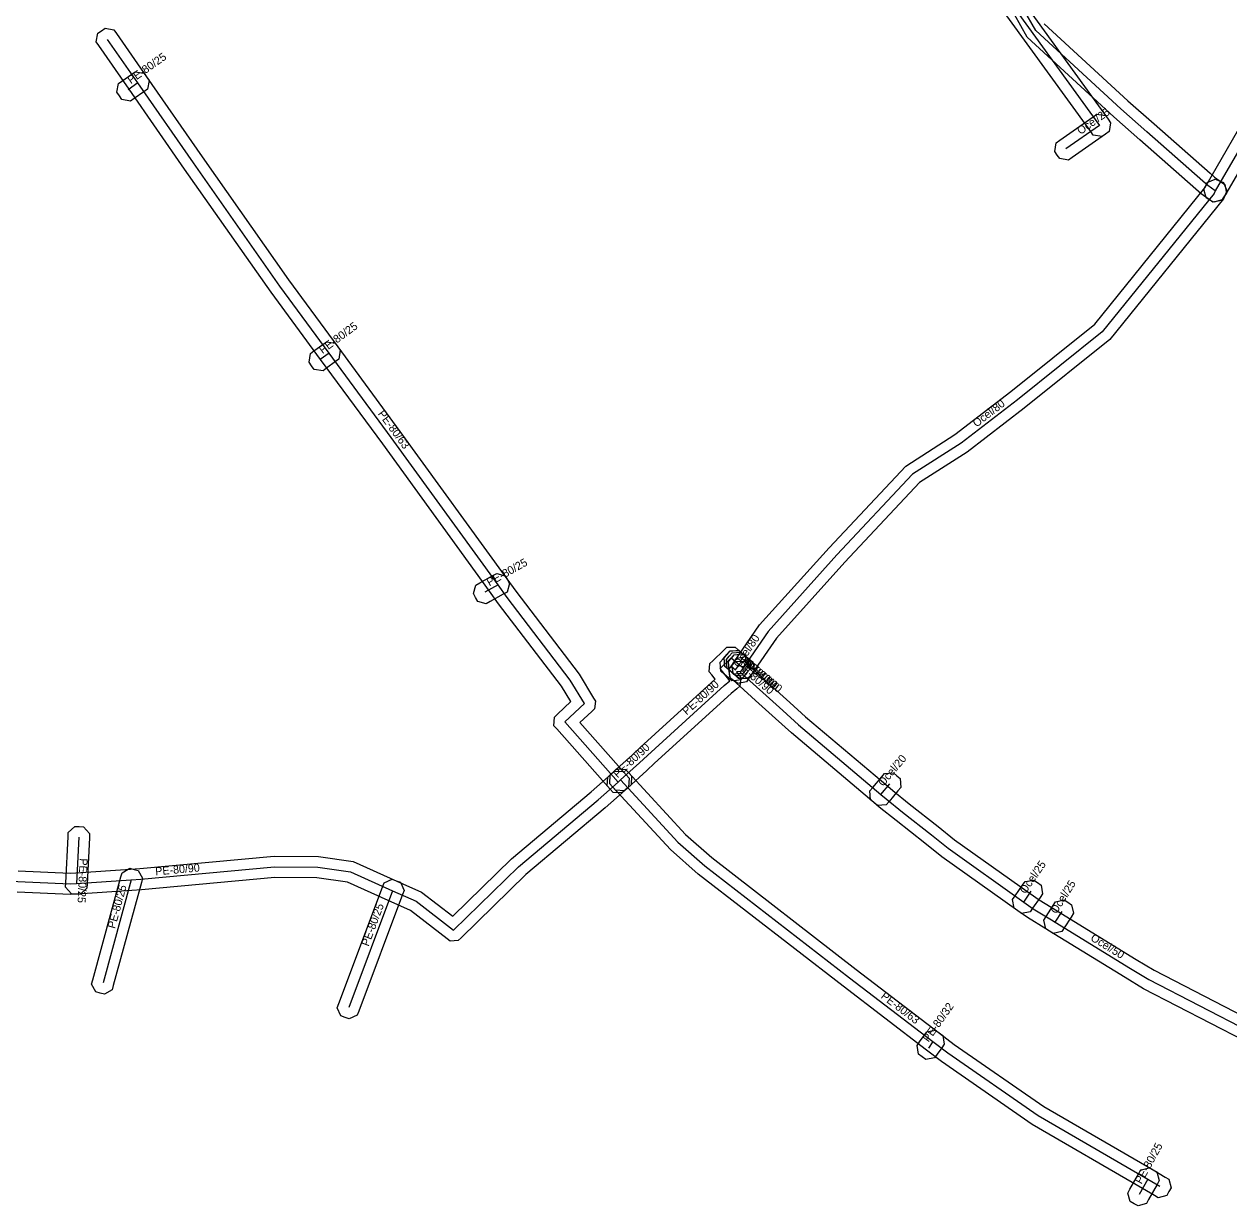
# Model space of a CAD drawing. Extents: x -569373 to -565022, y -1135090 to -1131496.
# Drawn here: x -565532.3 to -565419.4, y -1134096.5 to -1133985.7 of the extents above; entities that cross this region are included whole.
import ezdxf

# ---------------------------------------------------------------- set-up
doc = ezdxf.new("R2010")
doc.units = 0
for name, color, linetype in [('1', 7, 'Continuous'), ('24', 7, 'Continuous'), ('30', 7, 'Continuous')]:
    doc.layers.add(name, color=color, linetype=linetype)

msp = doc.modelspace()

# ---------------------------------------------------------------- linework, layer by layer
at = {"layer": '1'}
for points in [[(-565440.45, -1133981.063), (-565430.679, -1133994.584), (-565430.437, -1133994.92), (-565430.568, -1133995.738), (-565430.904, -1133995.981), (-565431.24, -1133996.223), (-565432.058, -1133996.092), (-565432.301, -1133995.756), (-565442.07, -1133982.237)], [(-565436.667, -1133985.641), (-565428.811, -1133992.877), (-565426.369, -1133995.03), (-565421.117, -1133999.661), (-565420.709, -1134000.024), (-565420.057, -1134000.481), (-565419.717, -1134000.718), (-565419.573, -1134001.534), (-565419.811, -1134001.873), (-565420.048, -1134002.213), (-565420.864, -1134002.357), (-565421.203, -1134002.119), (-565421.951, -1134001.596), (-565422.443, -1134001.159), (-565427.691, -1133996.53), (-565430.149, -1133994.363), (-565438.253, -1133986.899), (-565439.46, -1133984.762)], [(-565417.887, -1134080.99), (-565427.351, -1134076.122), (-565429.086, -1134075.056), (-565436.153, -1134070.713), (-565436.507, -1134070.496), (-565438.239, -1134069.436), (-565439.148, -1134068.796), (-565446.271, -1134063.729), (-565447.853, -1134062.473), (-565450.553, -1134060.323), (-565452.126, -1134059.072), (-565452.618, -1134058.652), (-565460.349, -1134052.113), (-565461.841, -1134050.762), (-565463.71, -1134049.073), (-565465.2, -1134047.733), (-565465.831, -1134047.162), (-565466.138, -1134046.884), (-565466.18, -1134046.056), (-565465.902, -1134045.749), (-565465.624, -1134045.442), (-565464.796, -1134045.4), (-565464.489, -1134045.678), (-565463.86, -1134046.247), (-565462.37, -1134047.587), (-565460.499, -1134049.278), (-565459.031, -1134050.607), (-565451.322, -1134057.128), (-565450.854, -1134057.528), (-565449.307, -1134058.757), (-565446.607, -1134060.907), (-565445.069, -1134062.131), (-565437.992, -1134067.164), (-565437.141, -1134067.764), (-565435.463, -1134068.79), (-565435.107, -1134069.007), (-565428.038, -1134073.352), (-565426.369, -1134074.378), (-565416.973, -1134079.21)], [(-565532.823, -1134065.052), (-565527.962, -1134065.268), (-565527.437, -1134065.232), (-565522.307, -1134064.892), (-565521.429, -1134064.833), (-565508.852, -1134063.69), (-565504.675, -1134063.721), (-565501.42, -1134064.19), (-565497.342, -1134066.007), (-565495.023, -1134067.046), (-565492.098, -1134069.298), (-565486.602, -1134063.929), (-565479.115, -1134057.634), (-565477.266, -1134055.984), (-565476.957, -1134055.708), (-565476.13, -1134055.755), (-565475.854, -1134056.064), (-565475.578, -1134056.373), (-565475.625, -1134057.2), (-565475.934, -1134057.476), (-565477.805, -1134059.146), (-565485.258, -1134065.411), (-565491.321, -1134071.335), (-565491.588, -1134071.596), (-565492.334, -1134071.64), (-565492.63, -1134071.412), (-565496.057, -1134068.774), (-565498.158, -1134067.833), (-565501.98, -1134066.13), (-565504.825, -1134065.719), (-565508.768, -1134065.69), (-565521.271, -1134066.827), (-565522.173, -1134066.888), (-565527.303, -1134067.228), (-565527.938, -1134067.272), (-565532.937, -1134067.048)]]:
    msp.add_lwpolyline(points, dxfattribs=at)
for points in [[(-565477.073, -1134057.703), (-565477.348, -1134057.393), (-565482.348, -1134051.753), (-565482.618, -1134051.449), (-565482.579, -1134050.635), (-565482.281, -1134050.358), (-565481.027, -1134049.191), (-565481.907, -1134047.734), (-565487.803, -1134040.026), (-565488.661, -1134038.836), (-565498.668, -1134025.03), (-565504.496, -1134017.102), (-565509.122, -1134010.814), (-565517.23, -1133999.263), (-565522.441, -1133991.76), (-565525.272, -1133987.68), (-565525.508, -1133987.34), (-565525.36, -1133986.524), (-565525.02, -1133986.288), (-565524.68, -1133986.052), (-565523.864, -1133986.2), (-565523.628, -1133986.54), (-565520.799, -1133990.62), (-565515.59, -1133998.117), (-565507.498, -1134009.646), (-565502.884, -1134015.918), (-565497.052, -1134023.85), (-565487.039, -1134037.664), (-565486.197, -1134038.834), (-565480.253, -1134046.606), (-565478.894, -1134048.853), (-565478.71, -1134049.157), (-565478.809, -1134049.86), (-565479.069, -1134050.102), (-565480.204, -1134051.157), (-565475.852, -1134056.067), (-565475.577, -1134056.377), (-565475.627, -1134057.203), (-565475.937, -1134057.478), (-565476.247, -1134057.753)], [(-565520.706, -1133991.77), (-565521.045, -1133992.008), (-565521.955, -1133992.648), (-565522.294, -1133992.886), (-565523.11, -1133992.744), (-565523.348, -1133992.405), (-565523.586, -1133992.066), (-565523.444, -1133991.25), (-565523.105, -1133991.012), (-565522.195, -1133990.372), (-565521.856, -1133990.134), (-565521.04, -1133990.276), (-565520.802, -1133990.615), (-565520.564, -1133990.954)], [(-565415.067, -1133993.714), (-565415.275, -1133994.072), (-565419.765, -1134001.802), (-565419.973, -1134002.16), (-565420.774, -1134002.373), (-565421.132, -1134002.165), (-565421.49, -1134001.957), (-565421.703, -1134001.156), (-565421.495, -1134000.798), (-565417.005, -1133993.068), (-565416.797, -1133992.71), (-565415.996, -1133992.497), (-565415.638, -1133992.705), (-565415.28, -1133992.913)], [(-565430.576, -1133995.75), (-565430.915, -1133995.988), (-565434.045, -1133998.188), (-565434.384, -1133998.426), (-565435.2, -1133998.284), (-565435.438, -1133997.945), (-565435.676, -1133997.606), (-565435.534, -1133996.79), (-565435.195, -1133996.552), (-565432.065, -1133994.352), (-565431.726, -1133994.114), (-565430.91, -1133994.256), (-565430.672, -1133994.595), (-565430.434, -1133994.934)], [(-565419.548, -1134001.303), (-565419.707, -1134001.685), (-565419.862, -1134002.057), (-565430.51, -1134015.232), (-565438.542, -1134021.676), (-565443.884, -1134025.789), (-565448.356, -1134028.655), (-565455.354, -1134036.117), (-565461.763, -1134043.24), (-565464.065, -1134046.596), (-565464.299, -1134046.937), (-565465.114, -1134047.089), (-565465.456, -1134046.855), (-565465.797, -1134046.621), (-565465.949, -1134045.806), (-565465.715, -1134045.464), (-565463.337, -1134042), (-565456.826, -1134034.763), (-565449.644, -1134027.105), (-565445.036, -1134024.151), (-565439.778, -1134020.104), (-565431.93, -1134013.808), (-565421.598, -1134001.023), (-565421.553, -1134000.915), (-565421.394, -1134000.533), (-565420.627, -1134000.218), (-565420.245, -1134000.377), (-565419.863, -1134000.536)], [(-565502.764, -1134017.071), (-565503.098, -1134017.316), (-565503.928, -1134017.926), (-565504.262, -1134018.171), (-565505.081, -1134018.046), (-565505.326, -1134017.712), (-565505.571, -1134017.378), (-565505.446, -1134016.559), (-565505.112, -1134016.314), (-565504.282, -1134015.704), (-565503.948, -1134015.459), (-565503.129, -1134015.584), (-565502.884, -1134015.918), (-565502.639, -1134016.252)], [(-565487.002, -1134038.923), (-565487.364, -1134039.124), (-565488.604, -1134039.814), (-565488.966, -1134040.015), (-565489.763, -1134039.788), (-565489.964, -1134039.426), (-565490.165, -1134039.064), (-565489.938, -1134038.267), (-565489.576, -1134038.066), (-565488.336, -1134037.376), (-565487.974, -1134037.175), (-565487.177, -1134037.402), (-565486.976, -1134037.764), (-565486.775, -1134038.126)], [(-565474.54, -1134053.497), (-565467.507, -1134047.098), (-565467.821, -1134046.692), (-565468.055, -1134046.39), (-565468.001, -1134045.629), (-565467.727, -1134045.363), (-565466.697, -1134044.363), (-565466.417, -1134044.092), (-565465.638, -1134044.07), (-565465.344, -1134044.325), (-565464.964, -1134044.655), (-565464.651, -1134044.927), (-565464.593, -1134045.753), (-565464.865, -1134046.066), (-565465.137, -1134046.379), (-565465.514, -1134046.405), (-565465.349, -1134046.618), (-565465.105, -1134046.933), (-565465.185, -1134047.726), (-565465.486, -1134047.986), (-565465.996, -1134048.428), (-565473.18, -1134054.963), (-565473.912, -1134055.655), (-565475.701, -1134057.264), (-565476.009, -1134057.541), (-565476.837, -1134057.497), (-565477.114, -1134057.189), (-565477.391, -1134056.881), (-565477.347, -1134056.053), (-565477.039, -1134055.776), (-565475.268, -1134054.185)], [(-565464.957, -1134044.662), (-565464.888, -1134044.724), (-565464.88, -1134044.723), (-565464.566, -1134044.993), (-565464.253, -1134045.264), (-565464.193, -1134046.09), (-565464.463, -1134046.404), (-565464.646, -1134046.615), (-565464.829, -1134046.837), (-565465.096, -1134047.16), (-565465.513, -1134047.196), (-565465.931, -1134047.233), (-565466.249, -1134046.961), (-565466.659, -1134046.611), (-565466.978, -1134046.338), (-565467.008, -1134045.919), (-565467.037, -1134045.501), (-565466.758, -1134045.187), (-565466.368, -1134044.747), (-565466.093, -1134044.437), (-565465.267, -1134044.387)], [(-565465.288, -1134044.38), (-565464.972, -1134044.648), (-565464.772, -1134044.818), (-565464.456, -1134045.086), (-565464.39, -1134045.912), (-565464.658, -1134046.228), (-565464.926, -1134046.544), (-565465.752, -1134046.61), (-565466.068, -1134046.342), (-565466.268, -1134046.172), (-565466.584, -1134045.904), (-565466.65, -1134045.078), (-565466.382, -1134044.762), (-565466.114, -1134044.446)], [(-565465.088, -1134044.55), (-565464.772, -1134044.818), (-565464.572, -1134044.988), (-565464.256, -1134045.256), (-565464.19, -1134046.082), (-565464.458, -1134046.398), (-565464.726, -1134046.714), (-565465.552, -1134046.78), (-565465.868, -1134046.512), (-565466.068, -1134046.342), (-565466.384, -1134046.074), (-565466.45, -1134045.248), (-565466.182, -1134044.932), (-565465.914, -1134044.616)], [(-565465.304, -1134047.03), (-565465.596, -1134046.738), (-565465.597, -1134046.737), (-565465.86, -1134046.518), (-565466.178, -1134046.253), (-565466.253, -1134045.428), (-565465.988, -1134045.11), (-565465.723, -1134044.792), (-565464.898, -1134044.717), (-565464.58, -1134044.982), (-565464.245, -1134045.261), (-565464.183, -1134045.323), (-565463.89, -1134045.616), (-565463.89, -1134046.444), (-565464.183, -1134046.737), (-565464.476, -1134047.03)], [(-565463.832, -1134046.259), (-565464.068, -1134046.599), (-565464.338, -1134046.989), (-565464.574, -1134047.329), (-565465.389, -1134047.478), (-565465.729, -1134047.242), (-565466.069, -1134047.006), (-565466.218, -1134046.191), (-565465.982, -1134045.851), (-565465.712, -1134045.461), (-565465.476, -1134045.121), (-565464.661, -1134044.972), (-565464.321, -1134045.208), (-565463.981, -1134045.444)], [(-565477.58, -1134056.271), (-565477.274, -1134055.992), (-565477.044, -1134055.782), (-565476.738, -1134055.502), (-565475.911, -1134055.54), (-565475.632, -1134055.846), (-565475.352, -1134056.152), (-565475.39, -1134056.979), (-565475.696, -1134057.258), (-565475.926, -1134057.468), (-565476.232, -1134057.748), (-565477.059, -1134057.71), (-565477.338, -1134057.404), (-565477.618, -1134057.098)], [(-565475.915, -1134055.538), (-565475.634, -1134055.843), (-565470.3, -1134061.634), (-565467.823, -1134063.808), (-565454.29, -1134074.288), (-565446.482, -1134080.266), (-565445.101, -1134081.321), (-565436.703, -1134087.135), (-565426.456, -1134093.096), (-565425.326, -1134093.756), (-565424.968, -1134093.965), (-565424.757, -1134094.767), (-565424.966, -1134095.124), (-565425.175, -1134095.482), (-565425.977, -1134095.693), (-565426.334, -1134095.484), (-565427.464, -1134094.824), (-565437.777, -1134088.825), (-565446.279, -1134082.939), (-565447.698, -1134081.854), (-565455.51, -1134075.872), (-565469.097, -1134065.352), (-565471.7, -1134063.066), (-565477.106, -1134057.197), (-565477.386, -1134056.893), (-565477.352, -1134056.065), (-565477.047, -1134055.784), (-565476.743, -1134055.504)], [(-565453.001, -1134057.559), (-565452.733, -1134057.243), (-565451.893, -1134056.253), (-565451.625, -1134055.937), (-565450.799, -1134055.869), (-565450.483, -1134056.137), (-565450.167, -1134056.405), (-565450.099, -1134057.231), (-565450.367, -1134057.547), (-565451.207, -1134058.537), (-565451.475, -1134058.853), (-565452.301, -1134058.921), (-565452.617, -1134058.653), (-565452.933, -1134058.385)], [(-565526.141, -1134061.545), (-565526.161, -1134061.959), (-565526.371, -1134066.279), (-565526.391, -1134066.692), (-565527.005, -1134067.249), (-565527.419, -1134067.229), (-565527.832, -1134067.209), (-565528.389, -1134066.595), (-565528.369, -1134066.181), (-565528.159, -1134061.861), (-565528.139, -1134061.448), (-565527.525, -1134060.891), (-565527.111, -1134060.911), (-565526.698, -1134060.931)], [(-565521.166, -1134065.754), (-565521.275, -1134066.154), (-565523.915, -1134075.814), (-565524.024, -1134076.213), (-565524.744, -1134076.624), (-565525.144, -1134076.515), (-565525.543, -1134076.406), (-565525.954, -1134075.686), (-565525.845, -1134075.286), (-565523.205, -1134065.626), (-565523.096, -1134065.227), (-565522.376, -1134064.816), (-565521.976, -1134064.925), (-565521.577, -1134065.034)], [(-565496.668, -1134066.882), (-565496.813, -1134067.27), (-565500.903, -1134078.2), (-565501.048, -1134078.588), (-565501.802, -1134078.932), (-565502.19, -1134078.787), (-565502.578, -1134078.642), (-565502.922, -1134077.888), (-565502.777, -1134077.5), (-565498.687, -1134066.57), (-565498.542, -1134066.182), (-565497.788, -1134065.838), (-565497.4, -1134065.983), (-565497.012, -1134066.128)], [(-565439.628, -1134067.75), (-565439.392, -1134067.41), (-565438.692, -1134066.4), (-565438.456, -1134066.06), (-565437.64, -1134065.912), (-565437.3, -1134066.148), (-565436.96, -1134066.384), (-565436.812, -1134067.2), (-565437.048, -1134067.54), (-565437.748, -1134068.55), (-565437.984, -1134068.89), (-565438.8, -1134069.038), (-565439.14, -1134068.802), (-565439.48, -1134068.566)], [(-565436.697, -1134069.675), (-565436.475, -1134069.325), (-565435.835, -1134068.315), (-565435.613, -1134067.965), (-565434.805, -1134067.783), (-565434.455, -1134068.005), (-565434.105, -1134068.227), (-565433.923, -1134069.035), (-565434.145, -1134069.385), (-565434.785, -1134070.395), (-565435.007, -1134070.745), (-565435.815, -1134070.927), (-565436.165, -1134070.705), (-565436.515, -1134070.483)], [(-565446.034, -1134081.298), (-565446.273, -1134081.636), (-565446.703, -1134082.246), (-565446.942, -1134082.584), (-565447.758, -1134082.726), (-565448.096, -1134082.487), (-565448.434, -1134082.248), (-565448.576, -1134081.432), (-565448.337, -1134081.094), (-565447.907, -1134080.484), (-565447.668, -1134080.146), (-565446.852, -1134080.004), (-565446.514, -1134080.243), (-565446.176, -1134080.482)], [(-565425.885, -1134094.081), (-565426.085, -1134094.444), (-565426.875, -1134095.874), (-565427.075, -1134096.236), (-565427.871, -1134096.465), (-565428.234, -1134096.265), (-565428.596, -1134096.065), (-565428.825, -1134095.269), (-565428.625, -1134094.906), (-565427.835, -1134093.476), (-565427.635, -1134093.114), (-565426.839, -1134092.885), (-565426.476, -1134093.085), (-565426.114, -1134093.285)]]:
    msp.add_lwpolyline(points, close=True, dxfattribs=at)
at = {"layer": '24'}
for points in [[(-565420.71, -1133879.09), (-565425.16, -1133893.1), (-565425.84, -1133895.26), (-565425.96, -1133895.86), (-565427, -1133901.26), (-565427.73, -1133905.48), (-565429.89, -1133917.94), (-565431.22, -1133925), (-565431.56, -1133927.21), (-565434.02, -1133935.35), (-565434.9, -1133938.25), (-565441.28, -1133953.93), (-565444.96, -1133961.25), (-565444.46, -1133966.54), (-565443.52, -1133978.54), (-565441.26, -1133981.65), (-565431.49, -1133995.17)], [(-565420.63, -1134001.3), (-565421.33, -1134000.81), (-565421.78, -1134000.41), (-565427.03, -1133995.78), (-565429.48, -1133993.62), (-565437.46, -1133986.27), (-565438.59, -1133984.27), (-565440.77, -1133980.42), (-565446.43, -1133969.32), (-565447.37, -1133967.56), (-565452.18, -1133958.56), (-565456.45, -1133955.46), (-565458.091, -1133954.322), (-565459.958, -1133953.028), (-565461.6, -1133951.89), (-565466.84, -1133948.57), (-565468.53, -1133947.5), (-565477.83, -1133941.92), (-565491.31, -1133933.86), (-565493.715, -1133932.311), (-565498.14, -1133929.46)], [(-565476.6, -1134056.73), (-565481.6, -1134051.09), (-565479.75, -1134049.37), (-565481.08, -1134047.17), (-565487, -1134039.43), (-565487.85, -1134038.25), (-565497.86, -1134024.44), (-565503.69, -1134016.51), (-565508.31, -1134010.23), (-565516.41, -1133998.69), (-565521.62, -1133991.19), (-565524.45, -1133987.11)], [(-565521.62, -1133991.19), (-565522.53, -1133991.83)], [(-565416.14, -1133993.57), (-565420.63, -1134001.3)], [(-565431.49, -1133995.17), (-565434.62, -1133997.37)], [(-565420.63, -1134001.3), (-565420.73, -1134001.54), (-565431.22, -1134014.52), (-565439.16, -1134020.89), (-565444.46, -1134024.97), (-565449, -1134027.88), (-565456.09, -1134035.44), (-565462.55, -1134042.62), (-565464.89, -1134046.03)], [(-565503.69, -1134016.51), (-565504.52, -1134017.12)], [(-565487.85, -1134038.25), (-565489.09, -1134038.94)], [(-565476.37, -1134056.52), (-565474.59, -1134054.92), (-565473.86, -1134054.23), (-565466.66, -1134047.68), (-565466.14, -1134047.23), (-565467.03, -1134046.08), (-565466, -1134045.08), (-565465.62, -1134045.41)], [(-565465.62, -1134045.41), (-565466.01, -1134045.85), (-565465.6, -1134046.2), (-565465.41, -1134045.97), (-565465.22, -1134045.75)], [(-565465.62, -1134045.41), (-565465.42, -1134045.58)], [(-565465.42, -1134045.58), (-565465.22, -1134045.75)], [(-565465.22, -1134045.75), (-565464.92, -1134046), (-565464.89, -1134046.03)], [(-565464.89, -1134046.03), (-565465.16, -1134046.42)], [(-565465.16, -1134046.42), (-565464.53, -1134046.99), (-565463.04, -1134048.33), (-565461.17, -1134050.02), (-565459.69, -1134051.36), (-565451.97, -1134057.89), (-565451.49, -1134058.3), (-565449.93, -1134059.54), (-565447.23, -1134061.69), (-565445.67, -1134062.93), (-565438.57, -1134067.98), (-565437.69, -1134068.6), (-565435.985, -1134069.643), (-565435.63, -1134069.86), (-565428.562, -1134074.204), (-565426.86, -1134075.25), (-565417.43, -1134080.1)], [(-565569.41, -1134068.2), (-565566.33, -1134067.78), (-565565.41, -1134067.82), (-565564.09, -1134067.88), (-565557.88, -1134068.47), (-565553.76, -1134068.29), (-565549.45, -1134067.28), (-565545.53, -1134065.83), (-565542.53, -1134065.38), (-565532.88, -1134066.05), (-565527.95, -1134066.27), (-565527.37, -1134066.23), (-565522.24, -1134065.89), (-565521.35, -1134065.83), (-565508.81, -1134064.69), (-565504.75, -1134064.72), (-565501.7, -1134065.16), (-565497.75, -1134066.92), (-565495.54, -1134067.91), (-565492.02, -1134070.62), (-565485.93, -1134064.67), (-565478.46, -1134058.39), (-565476.6, -1134056.73)], [(-565476.6, -1134056.73), (-565476.37, -1134056.52)], [(-565476.37, -1134056.52), (-565471, -1134062.35), (-565468.46, -1134064.58), (-565454.9, -1134075.08), (-565447.09, -1134081.06), (-565445.69, -1134082.13), (-565437.24, -1134087.98), (-565426.96, -1134093.96), (-565425.83, -1134094.62)], [(-565451.97, -1134057.89), (-565451.13, -1134056.9)], [(-565527.16, -1134061.91), (-565527.37, -1134066.23)], [(-565522.24, -1134065.89), (-565524.88, -1134075.55)], [(-565497.75, -1134066.92), (-565501.84, -1134077.85)], [(-565438.57, -1134067.98), (-565437.87, -1134066.97)], [(-565435.63, -1134069.86), (-565434.99, -1134068.85)], [(-565447.09, -1134081.06), (-565447.52, -1134081.67)], [(-565426.96, -1134093.96), (-565427.75, -1134095.39)]]:
    msp.add_lwpolyline(points, dxfattribs=at)

# ---------------------------------------------------------------- texts
at = {"layer": '30'}
for s, rotation, p in [('PE-80/25', 35.11859, (-565522.275, -1133991.31)), ('Ocel/25', 35.10244, (-565433.255, -1133996.07)), ('PE-80/25', 36.31365, (-565504.305, -1134016.615)), ('PE-80/63', 306.32269, (-565499.155, -1134022.207)), ('Ocel/80', 37.58948, (-565443.009, -1134023.499)), ('PE-80/25', 29.09382, (-565488.67, -1134038.395)), ('Ocel/80', 55.30485, (-565465.253, -1134046.066)), ('PE-80/90', 319.51399, (-565465.567, -1134045.858)), ('PE-80/90', 319.63546, (-565465.282, -1134045.327)), ('PE-80/90', 319.63546, (-565465.082, -1134045.497)), ('PE-80/90', 320.19443, (-565464.815, -1134045.721)), ('PE-80/90', 42.29349, (-565470.17, -1134050.492)), ('PE-80/90', 42.39744, (-565476.648, -1134056.391)), ('Ocel/20', 49.6859, (-565451.75, -1134057.195)), ('PE-80/25', 267.21698, (-565527.065, -1134063.87)), ('PE-80/90', 5.19443, (-565519.95, -1134065.485)), ('Ocel/25', 55.27536, (-565438.42, -1134067.275)), ('Ocel/25', 57.63906, (-565435.51, -1134069.155)), ('PE-80/25', 74.71477, (-565523.76, -1134070.52)), ('PE-80/25', 69.48418, (-565499.995, -1134072.185)), ('Ocel/50', 328.42507, (-565432.388, -1134071.529)), ('PE-80/63', 322.55926, (-565452.032, -1134076.923)), ('PE-80/32', 54.8193, (-565447.505, -1134081.165)), ('PE-80/25', 61.08165, (-565427.555, -1134094.475))]:
    msp.add_text(s, height=0.75, rotation=rotation, dxfattribs=at).set_placement(p)

doc.saveas('drawing.dxf')
